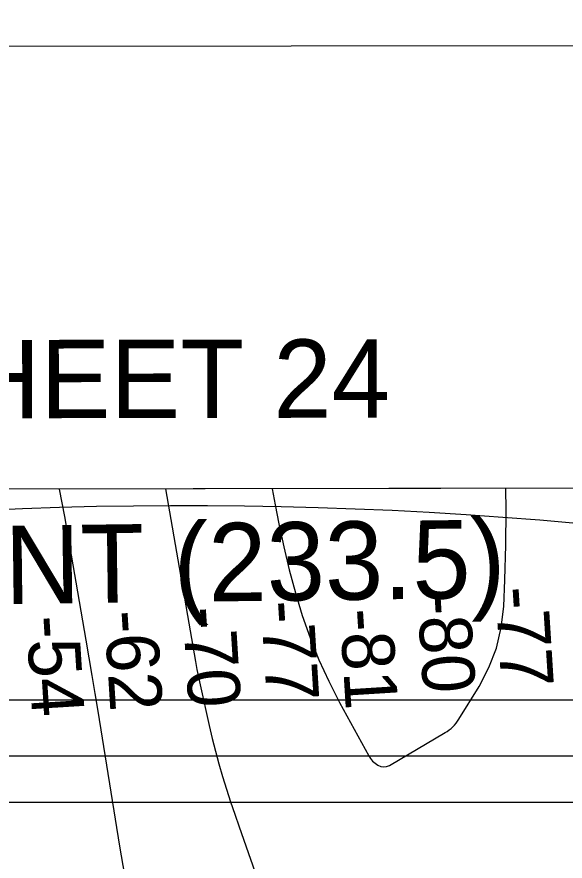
# Model space of a CAD drawing. Extents: x 3313447 to 3351316, y 703786 to 729172.
# Drawn here: x 3323798 to 3324497, y 726885 to 727963 of the extents above; entities that cross this region are included whole.
import ezdxf

# ---------------------------------------------------------------- set-up
doc = ezdxf.new("R2010")
doc.units = 0
for name, color, linetype in [('V-ANNO-SYMB', 7, 'Continuous'), ('V-ANNO-TEXT', 7, 'Continuous'), ('V-CHAN-NAID', 7, 'Continuous'), ('V-GRID-FRAM', 7, 'Continuous'), ('V-RIVR-RANG', 7, 'Continuous'), ('V-TOPO-DPTH', 7, 'Continuous'), ('V-TOPO-MINR', 7, 'Continuous'), ('V-UTIL-LINE', 7, 'Continuous')]:
    doc.layers.add(name, color=color, linetype=linetype)

msp = doc.modelspace()

# ---------------------------------------------------------------- linework, layer by layer
at = {"layer": 'V-ANNO-SYMB'}
msp.add_lwpolyline([(3316815.1, 704998.2), (3349898.2, 705046.3), (3349864.9, 727962.9), (3316781.7, 727914.8), (3316815.1, 704998.2)], dxfattribs=at)
at = {"layer": 'V-GRID-FRAM'}
msp.add_lwpolyline([(3317576.9, 727351), (3317595.4, 709166), (3349105.8, 709211.8), (3349071.4, 727396.8), (3317576.9, 727351)], dxfattribs=at)
at = {"layer": 'V-TOPO-DPTH'}
msp.add_lwpolyline([(3324639.1, 727361.3), (3323436.8, 727359.5), (3323417.7, 727093.6), (3323417.6, 727078.1), (3323417.6, 727062.7), (3323417.1, 726804.6)], dxfattribs=at)
at = {"layer": 'V-TOPO-MINR'}
for points in [[(3323851.7, 727360.1), (3323858.2, 727325.3), (3323885.7, 727167.3), (3323889.6, 727144.6), (3323893.4, 727122), (3323897.2, 727099.3), (3323900.9, 727076.6), (3323928.6, 726904.4), (3323945.3, 726808.2)], [(3323987.4, 727360.3), (3324023.7, 727149.9), (3324025.5, 727139.9), (3324027.4, 727130), (3324029.4, 727120.1), (3324031.6, 727110.3), (3324043.1, 727058.2), (3324047, 727041.8), (3324051.1, 727025.5), (3324055.5, 727009.3), (3324060.2, 726993.1), (3324065.2, 726977), (3324070.4, 726961), (3324075.7, 726945.1), (3324081.1, 726929.1), (3324136.1, 726772.2)], [(3324123.4, 727360.5), (3324127.3, 727340), (3324132, 727315.9), (3324138.3, 727286.3), (3324145.3, 727256.9), (3324153.2, 727227.7), (3324161.9, 727198.7), (3324171.9, 727170.1), (3324182.9, 727142.1), (3324195.6, 727114.7), (3324209.3, 727087.8), (3324246.7, 727019.7), (3324249, 727016.2), (3324251.6, 727012.9), (3324254.8, 727010.1), (3324258.2, 727007.6), (3324261.9, 727006.1), (3324265.6, 727005.4), (3324269.3, 727006), (3324273, 727007.4), (3324344.3, 727049.2), (3324346.9, 727050.8), (3324349.4, 727052.6), (3324351.8, 727054.6), (3324354.1, 727056.7), (3324356.2, 727058.9), (3324358.2, 727061.2), (3324360, 727063.7), (3324361.7, 727066.3), (3324387.6, 727108.1), (3324400.1, 727132.2), (3324409.9, 727157.2), (3324415.8, 727183.4), (3324419.1, 727210.4), (3324420.5, 727244.1), (3324421.8, 727288.5), (3324422.1, 727333), (3324421.6, 727361)]]:
    msp.add_lwpolyline(points, dxfattribs=at)
at = {"layer": 'V-UTIL-LINE'}
for p, q in [((3321087.6, 727091.1), (3325881, 727091.1)), ((3321075.7, 727019.8), (3325928.6, 727019.8)), ((3321111.4, 726960.3), (3325857.2, 726960.3))]:
    msp.add_line(p, q, dxfattribs=at)
msp.add_lwpolyline([(3323757.7, 727333.2), (3323804.9, 727335.2), (3323852, 727336.9), (3323899.2, 727338.1), (3323946.4, 727338.9), (3323993.6, 727339.2), (3324040.8, 727339.2), (3324087.9, 727338.8), (3324135.1, 727338), (3324182.3, 727336.7), (3324229.4, 727335.1), (3324276.6, 727333), (3324323.7, 727330.5), (3324370.8, 727327.6), (3324417.9, 727324.4), (3324464.9, 727320.7), (3324511.9, 727316.6)], dxfattribs=at)

# ---------------------------------------------------------------- texts
at = {"layer": 'V-ANNO-TEXT'}
msp.add_text('JOINS SHEET 24', height=100, rotation=0.0833, dxfattribs=at).set_placement((3323211.1, 727449.7))
at = {"layer": 'V-CHAN-NAID'}
msp.add_text('FORMOSA - PLANT (233.5)', height=100, rotation=0.7252, dxfattribs=at).set_placement((3322735, 727200))
at = {"layer": 'V-RIVR-RANG'}
for s, p in [('-77', (3324408.1, 727234.3)), ('-80', (3324308.4, 727227)), ('-70', (3324009, 727208.6)), ('-77', (3324108.7, 727216.4)), ('-62', (3323909, 727204)), ('-81', (3324209.5, 727206.3)), ('-54', (3323809.3, 727197.2))]:
    msp.add_text(s, height=67, rotation=273.5618, dxfattribs=at).set_placement(p)

doc.saveas('drawing.dxf')
